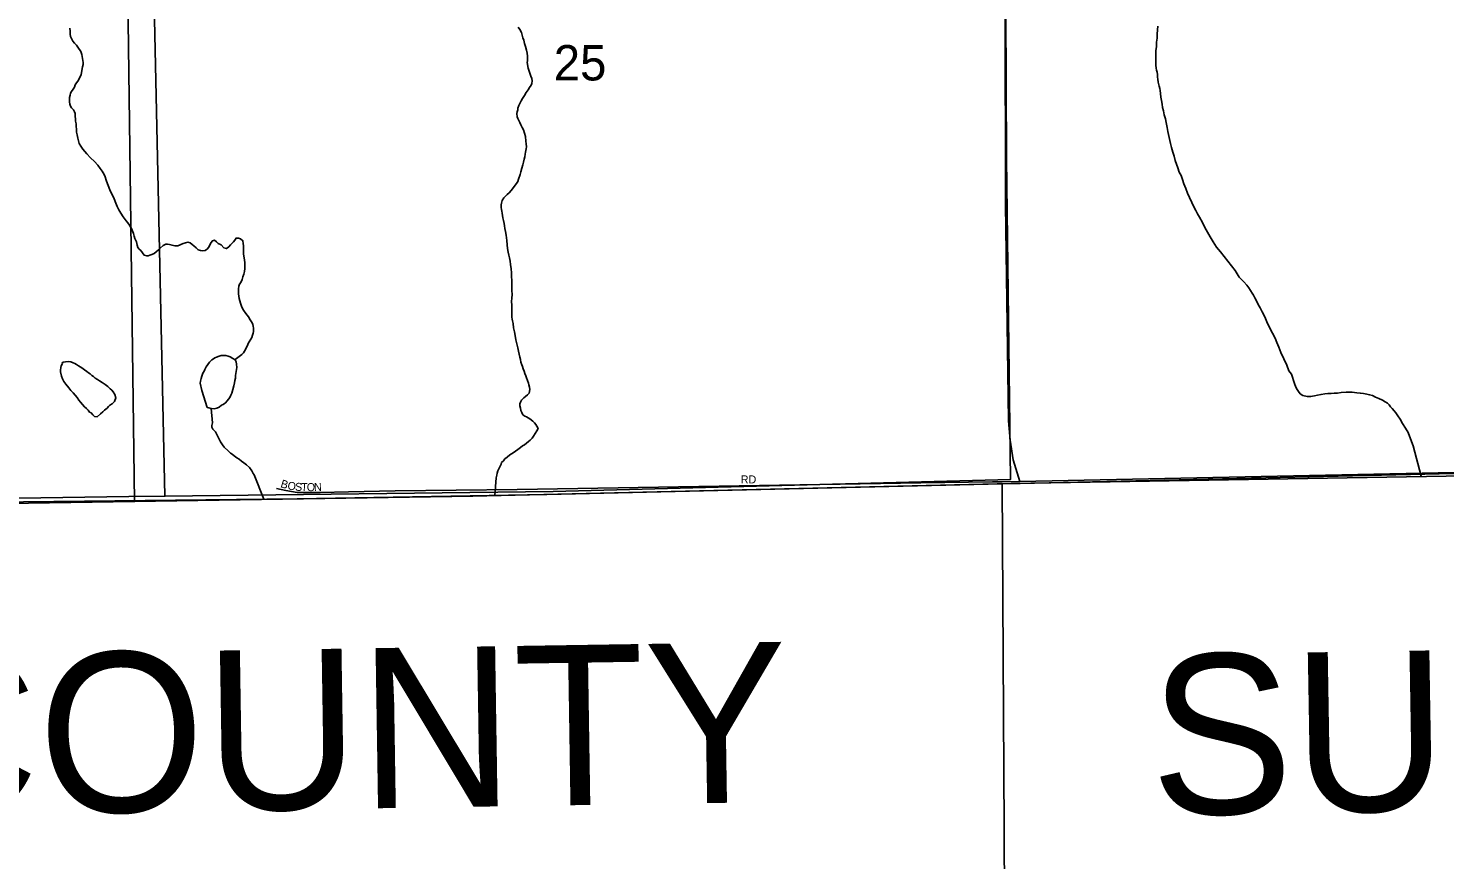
# Model space of a CAD drawing. Extents: x 2010165 to 2382125, y 1060529 to 1407316.
# Drawn here: x 2186541 to 2195389, y 1192490 to 1197681 of the extents above; entities that cross this region are included whole.
import ezdxf

# ---------------------------------------------------------------- set-up
doc = ezdxf.new("R2010")
doc.units = 0
for name, color, linetype in [('GM_X_Adjacent_County', 7, 'Continuous'), ('GM_X_Adjacent_County_Text', 7, 'Continuous'), ('GM_X_City_Street', 7, 'Continuous'), ('GM_X_City_Street_Text', 7, 'Continuous'), ('GM_X_Corporation', 7, 'Continuous'), ('GM_X_County', 7, 'Continuous'), ('GM_X_Major_River', 7, 'Continuous'), ('GM_X_Minor_Lake', 7, 'Continuous'), ('GM_X_Minor_River', 7, 'Continuous'), ('GM_X_Section', 7, 'Continuous'), ('GM_X_Section_Text', 7, 'Continuous'), ('GM_X_State_Route', 7, 'Continuous')]:
    doc.layers.add(name, color=color, linetype=linetype)

msp = doc.modelspace()

# ---------------------------------------------------------------- linework, layer by layer
at = {"layer": 'GM_X_Adjacent_County'}
for points in [[(2192594.1, 1158494.9), (2192604.3, 1162456.4), (2192620.3, 1166969.1), (2192629.9, 1167519.5), (2192631.2, 1170403.5), (2192632.8, 1173672.8), (2192633.8, 1175629.5), (2192671.1, 1181169.3), (2192669.3, 1184775.1), (2192667.8, 1187766.9), (2192660.9, 1188884.7), (2192638, 1192623.1), (2192637, 1192687), (2192624.5, 1194837.8), (2192737.6, 1194839.7), (2198605.6, 1194974.2)], [(2192671.1, 1181169.3), (2192669.3, 1184775.1), (2192667.8, 1187766.9), (2192660.9, 1188884.7), (2192638, 1192623.1), (2192637, 1192687), (2192624.5, 1194837.8), (2192096.3, 1194825.3), (2189780.1, 1194770.1), (2188219.8, 1194742.8), (2183281.7, 1194689.2), (2183037.7, 1194685.2), (2182925.1, 1194679.5), (2182885.3, 1194673), (2182859.5, 1194657.8), (2180868.9, 1194626.6), (2178432, 1194588.4)]]:
    msp.add_lwpolyline(points, dxfattribs=at)
at = {"layer": 'GM_X_City_Street'}
for points in [[(2192734.1, 1194851.8), (2196656.4, 1194933.6)], [(2188364.8, 1194783.1), (2188542, 1194786.7), (2188832, 1194792.7), (2189593.9, 1194801.8), (2192115.6, 1194843.8), (2192565.3, 1194850), (2192624.1, 1194850.3), (2192734.1, 1194851.8)], [(2188091.4, 1194807.8), (2188150.3, 1194794.2), (2188221.4, 1194782.2), (2188223.3, 1194782.1), (2188303, 1194781.8), (2188364.8, 1194783.1)]]:
    msp.add_lwpolyline(points, dxfattribs=at)
at = {"layer": 'GM_X_Corporation'}
for points in [[(2204447.2, 1221938.7), (2204662.3, 1210529.8), (2204445.3, 1208317.3), (2199872.3, 1208332.6), (2199834.9, 1208326), (2199654.4, 1208314.4), (2199497, 1208304.3), (2197215.9, 1208288.2), (2196205.1, 1208275.6), (2196632.3, 1194905.5), (2192680.8, 1194838.8), (2189318.2, 1194759.1), (2187205, 1194725.9), (2187027.1, 1208132.6), (2187013.9, 1213879), (2186978.3, 1216841.2), (2186941.3, 1219753.4), (2186933.5, 1220238.7), (2186923.4, 1220744.1), (2186878.7, 1221701)], [(2186878.7, 1221701), (2186923.4, 1220744.1), (2186933.5, 1220238.7), (2186941.3, 1219753.4), (2186978.3, 1216841.2), (2187013.9, 1213879), (2187027.1, 1208132.6), (2187205, 1194725.9), (2177123.5, 1194567.9), (2176176.5, 1194580.3), (2174206.9, 1194531), (2167776.4, 1194381.4), (2165054.7, 1194304.8), (2164968.9, 1199659.4), (2164935.2, 1207756.2), (2164931.8, 1207897.8), (2164930.1, 1208081.5), (2164898.5, 1211429), (2164844.7, 1216037.6), (2164832.8, 1218637), (2164895.8, 1221436.7)]]:
    msp.add_lwpolyline(points, dxfattribs=at)
at = {"layer": 'GM_X_County'}
msp.add_lwpolyline([(2198605.6, 1194974.2), (2192737.6, 1194839.7), (2192624.5, 1194837.8), (2192096.3, 1194825.3), (2189780.1, 1194770.1), (2188219.8, 1194742.8), (2183281.7, 1194689.2), (2183037.7, 1194685.2), (2182925.1, 1194679.5), (2182885.3, 1194673), (2182859.5, 1194657.8), (2180868.9, 1194626.6), (2178432, 1194588.4)], dxfattribs=at)
at = {"layer": 'GM_X_Major_River'}
for points in [[(2186821.4, 1197302.3), (2186829.1, 1197314.6), (2186834.7, 1197328.8), (2186842.4, 1197341), (2186850.1, 1197351.3), (2186855.9, 1197361.5), (2186861.6, 1197371.7), (2186867.4, 1197381.8), (2186871, 1197394), (2186879.8, 1197440.4), (2186883.4, 1197456.6), (2186883.1, 1197468.6), (2186882.7, 1197480.6), (2186880.4, 1197492.6), (2186878, 1197506.6), (2186875.7, 1197518.6), (2186871.4, 1197530.5), (2186867.1, 1197540.5), (2186858.8, 1197552.3), (2186850.4, 1197564.1), (2186842.1, 1197575.9), (2186829.7, 1197589.7), (2186819.3, 1197601.4), (2186810.9, 1197617.3), (2186804.5, 1197631.2), (2186802.1, 1197645.2), (2186801.6, 1197663.2), (2186801.1, 1197683.3)], [(2187823.6, 1196348.8), (2187813.8, 1196340.5), (2187804.1, 1196330.2), (2187794.4, 1196317.9), (2187778.7, 1196305.5), (2187762.5, 1196311.1), (2187746, 1196328.7), (2187727.7, 1196338.3), (2187717.4, 1196348), (2187705.1, 1196357.8), (2187691.1, 1196355.4), (2187683.4, 1196343.1), (2187677.7, 1196332.9), (2187670.1, 1196318.7), (2187660.4, 1196304.4), (2187646.7, 1196294), (2187630.7, 1196291.5), (2187616.6, 1196293.2), (2187602.4, 1196298.8), (2187590.1, 1196310.6), (2187575.7, 1196322.2), (2187565.4, 1196332), (2187553.1, 1196341.7), (2187537, 1196345.3), (2187523, 1196342.9), (2187509.1, 1196338.5), (2187475.4, 1196323.6), (2187457.4, 1196323.1), (2187439.2, 1196326.7), (2187423, 1196332.3), (2187411, 1196333.9), (2187400.9, 1196333.7), (2187383.1, 1196325.2), (2187365.5, 1196308.7), (2187353.8, 1196298.3), (2187340.1, 1196285.9), (2187326.3, 1196275.5), (2187312.5, 1196269.1), (2187300.5, 1196264.8), (2187290.6, 1196260.5), (2187280.6, 1196260.2), (2187264.4, 1196265.8), (2187254, 1196279.6), (2187243.6, 1196293.4), (2187233.3, 1196303.2), (2187225, 1196313), (2187220.7, 1196326.9), (2187216.1, 1196348.9), (2187207.5, 1196368.8), (2187203.1, 1196382.7), (2187198.6, 1196400.6), (2187194.3, 1196410.6), (2187187.9, 1196426.5), (2187181.6, 1196438.4), (2187173.2, 1196452.2), (2187162.8, 1196466), (2187152.4, 1196479.8), (2187133.7, 1196503.3), (2187119, 1196527.1), (2187106.4, 1196548.8), (2187095.8, 1196568.6), (2187087.2, 1196590.5), (2187076.5, 1196616.3), (2187050.9, 1196673.9), (2187040.2, 1196699.7), (2187029.4, 1196727.5), (2187018.4, 1196761.3), (2187007.9, 1196779.1), (2187001.7, 1196789), (2186989.2, 1196806.8), (2186974.6, 1196826.5), (2186953.9, 1196850), (2186929.2, 1196873.5), (2186906.5, 1196897), (2186881.6, 1196926.4), (2186869.1, 1196946.2), (2186858.6, 1196962), (2186854.2, 1196977.9), (2186849.7, 1196995.8), (2186847.2, 1197015.9), (2186842.7, 1197033.8), (2186842.2, 1197051.9), (2186839.7, 1197067.9), (2186839.2, 1197085.9), (2186836.8, 1197101.9), (2186836.4, 1197118), (2186834.1, 1197128), (2186833.8, 1197140), (2186833.5, 1197150), (2186829.2, 1197160), (2186822.9, 1197171.8), (2186810.5, 1197185.6), (2186804.2, 1197195.5), (2186799.9, 1197207.4), (2186799.4, 1197223.4), (2186799.1, 1197237.5), (2186798.7, 1197249.5), (2186802.4, 1197263.7), (2186804, 1197275.8), (2186811.7, 1197288), (2186821.4, 1197302.3)], [(2187832.4, 1195612.8), (2187874.7, 1195645.4), (2187884.4, 1195655.7), (2187892.2, 1195665.9), (2187897.9, 1195676.1), (2187903.6, 1195690.3), (2187909.3, 1195700.5), (2187915, 1195712.7), (2187938, 1195751.4), (2187941.6, 1195765.6), (2187945.3, 1195777.8), (2187947, 1195787.8), (2187946.8, 1195797.9), (2187948.5, 1195810), (2187946.1, 1195821.9), (2187943.9, 1195831.9), (2187939.6, 1195841.9), (2187927, 1195861.6), (2187916.5, 1195879.4), (2187908.2, 1195891.2), (2187899.9, 1195901.1), (2187885.3, 1195920.7), (2187874.8, 1195940.6), (2187866.1, 1195964.4), (2187859.3, 1195994.3), (2187854.4, 1196024.3), (2187853.6, 1196054.4), (2187857.2, 1196070.6), (2187860.9, 1196082.8), (2187868.6, 1196095), (2187876.1, 1196113.3), (2187881.7, 1196129.5), (2187887.3, 1196145.7), (2187890.8, 1196163.8), (2187894.3, 1196182), (2187893.8, 1196200.1), (2187893.3, 1196218.1), (2187888.5, 1196248.1), (2187885.9, 1196272.1), (2187885.3, 1196292.2), (2187884.8, 1196310.3), (2187884.5, 1196322.3), (2187884.1, 1196338.4), (2187881.6, 1196354.4), (2187867.3, 1196366), (2187853.1, 1196371.7), (2187839.1, 1196371.3), (2187831.4, 1196359.1), (2187823.6, 1196348.8)]]:
    msp.add_lwpolyline(points, dxfattribs=at)
at = {"layer": 'GM_X_Minor_Lake'}
for points in [[(2187615.1, 1195465.9), (2187616.5, 1195477.9), (2187620.1, 1195494.1), (2187625.7, 1195508.3), (2187631.2, 1195528.5), (2187638.9, 1195540.8), (2187644.6, 1195551), (2187652.2, 1195567.2), (2187661.9, 1195581.6), (2187673.5, 1195595.9), (2187687.1, 1195610.3), (2187697, 1195616.6), (2187706.9, 1195622.9), (2187716.8, 1195627.2), (2187732.6, 1195633.6), (2187746.6, 1195638), (2187756.6, 1195638.3), (2187774.6, 1195638.7), (2187788.7, 1195635.1), (2187802.9, 1195629.4), (2187819.2, 1195619.8), (2187833.5, 1195612.2), (2187839.9, 1195598.3), (2187842.2, 1195584.3), (2187842.8, 1195564.2), (2187836.1, 1195513.8), (2187834.6, 1195495.7), (2187831, 1195481.6), (2187829.4, 1195467.5), (2187825.8, 1195449.3), (2187818.5, 1195425), (2187813.1, 1195402.8), (2187805.4, 1195390.6), (2187799.7, 1195376.3), (2187784.2, 1195355.9), (2187772.5, 1195343.5), (2187758.8, 1195333.1), (2187748.9, 1195328.8), (2187733.2, 1195316.4), (2187719.3, 1195310), (2187701.4, 1195305.5), (2187683.3, 1195307), (2187669.2, 1195310.7), (2187659, 1195314.4), (2187624.1, 1195419.9)], [(2186755.3, 1195587.8), (2186745.7, 1195573.5), (2186744, 1195563.4), (2186742.4, 1195547.3), (2186742.7, 1195537.3), (2186747.4, 1195509.3), (2186753.9, 1195493.4), (2186762.4, 1195475.6), (2186774.8, 1195459.8), (2186793.5, 1195436.2), (2186806, 1195420.5), (2186820.4, 1195404.8), (2186832.8, 1195391.1), (2186845.3, 1195375.3), (2186855.7, 1195359.5), (2186868.1, 1195345.8), (2186880.5, 1195332.1), (2186892.9, 1195318.3), (2186905.3, 1195306.6), (2186915.6, 1195296.9), (2186923.9, 1195285), (2186934.1, 1195279.3), (2186944.4, 1195267.5), (2186954.7, 1195257.7), (2186970.8, 1195256.1), (2186992.4, 1195274.8), (2187006.1, 1195287.2), (2187017.8, 1195297.5), (2187033.5, 1195310), (2187041.3, 1195320.2), (2187051.1, 1195328.5), (2187064.9, 1195336.9), (2187078.5, 1195351.3), (2187088, 1195373.7), (2187081.3, 1195395.6), (2187070.9, 1195411.4), (2187062.6, 1195421.2), (2187052.3, 1195431), (2187037.9, 1195444.7), (2187021.6, 1195456.3), (2187003.1, 1195469.8), (2186984.8, 1195479.4), (2186972.5, 1195489.1), (2186958.3, 1195496.8), (2186948, 1195506.5), (2186937.8, 1195514.3), (2186927.5, 1195524.1), (2186917.3, 1195529.8), (2186907.1, 1195537.6), (2186892.7, 1195549.3), (2186876.4, 1195560.9), (2186854, 1195574.3), (2186841.7, 1195582.1), (2186831.5, 1195587.8), (2186821.4, 1195591.6), (2186807.2, 1195599.2), (2186791.1, 1195600.8), (2186773.1, 1195598.3), (2186759.1, 1195595.9), (2186751.3, 1195589.7)], [(2187624.1, 1195419.9), (2187615.1, 1195465.9)]]:
    msp.add_lwpolyline(points, dxfattribs=at)
at = {"layer": 'GM_X_Minor_River'}
for points in [[(2189527, 1196389.6), (2189522.3, 1196413.6), (2189517.8, 1196431.6), (2189515.4, 1196447.6), (2189512.9, 1196463.6), (2189508.5, 1196481.5), (2189506, 1196497.5), (2189503.6, 1196513.5), (2189501.2, 1196527.5), (2189498.9, 1196539.5), (2189496.6, 1196549.5), (2189494.2, 1196563.5), (2189495.8, 1196579.6), (2189497.5, 1196589.7), (2189501.1, 1196605.8), (2189510.7, 1196622.1), (2189532.2, 1196642.8), (2189543.9, 1196655.1), (2189557.5, 1196669.6), (2189590.5, 1196712.6), (2189598.1, 1196724.8), (2189603.8, 1196739), (2189613, 1196769.4), (2189618.6, 1196785.6), (2189624, 1196807.8), (2189629.4, 1196828.1), (2189635, 1196846.3), (2189638.5, 1196864.4), (2189642.1, 1196878.6), (2189645.7, 1196894.8), (2189647.3, 1196908.8), (2189649, 1196918.9), (2189650.8, 1196929), (2189652.5, 1196941.1), (2189652, 1196959.2), (2189649.5, 1196977.2), (2189646.7, 1197005.2), (2189640.1, 1197027.1), (2189633.6, 1197047), (2189627.1, 1197062.9), (2189618.7, 1197078.8), (2189612.3, 1197092.7), (2189605.9, 1197106.6), (2189599.6, 1197118.4), (2189595.3, 1197128.4), (2189592.7, 1197150.4), (2189594.4, 1197160.4), (2189598.1, 1197172.6), (2189599.8, 1197182.7), (2189605.4, 1197198.9), (2189613, 1197215.2), (2189620.6, 1197229.4), (2189628.3, 1197243.7), (2189639.8, 1197262), (2189651.3, 1197280.4), (2189662.9, 1197296.8), (2189672.6, 1197311.1), (2189682.1, 1197327.4), (2189685.9, 1197337.6), (2189689.5, 1197353.7), (2189687.1, 1197367.7), (2189680.6, 1197383.6), (2189674.1, 1197401.5), (2189667.6, 1197419.4), (2189663.3, 1197433.3), (2189658.3, 1197467.3), (2189660, 1197479.4), (2189659.6, 1197493.5), (2189659.2, 1197507.5), (2189656.8, 1197525.5), (2189652.2, 1197545.5), (2189647.6, 1197567.4), (2189641.1, 1197587.4), (2189636.5, 1197607.3), (2189630.1, 1197623.2), (2189625.6, 1197639.2), (2189621.2, 1197655.1), (2189612.6, 1197675), (2189602.2, 1197688.7)], [(2193596.4, 1197695.6), (2193595.1, 1197671.4), (2193593.8, 1197645.3), (2193592.5, 1197619.2), (2193589.1, 1197595), (2193587.8, 1197568.8), (2193584.6, 1197540.6), (2193585.2, 1197516.6), (2193583.9, 1197492.4), (2193584.4, 1197472.4), (2193584.9, 1197452.3), (2193587.5, 1197432.3), (2193589.8, 1197420.3), (2193592.2, 1197408.3), (2193594.6, 1197392.3), (2193595, 1197376.3), (2193597.4, 1197364.3), (2193599.8, 1197346.3), (2193602.1, 1197336.3), (2193604.6, 1197320.3), (2193608.9, 1197306.4), (2193611.3, 1197292.4), (2193613.8, 1197274.4), (2193616.4, 1197252.3), (2193619, 1197230.3), (2193623.6, 1197208.4), (2193626.2, 1197186.3), (2193632.8, 1197166.4), (2193637.5, 1197140.5), (2193644.1, 1197116.5), (2193648.8, 1197092.6), (2193655.6, 1197062.6), (2193660.3, 1197036.7), (2193676.3, 1196962.8), (2193683.1, 1196936.8), (2193691.8, 1196909), (2193698.6, 1196883.1), (2193705.3, 1196857.1), (2193713.9, 1196833.3), (2193722.6, 1196809.4), (2193731.3, 1196783.5), (2193741.9, 1196761.7), (2193750.6, 1196737.8), (2193759.4, 1196710), (2193772.1, 1196682.2), (2193783, 1196652.4), (2193795.8, 1196624.6), (2193808.6, 1196594.8), (2193821.4, 1196567), (2193834, 1196543.3), (2193844.6, 1196523.5), (2193857.2, 1196501.7), (2193876.2, 1196468.1), (2193891, 1196438.4), (2193907.9, 1196408.7), (2193924.7, 1196379), (2193943.6, 1196347.4), (2193964.5, 1196315.8), (2193989.4, 1196286.3), (2194012.2, 1196256.8), (2194035.1, 1196227.3), (2194057.9, 1196197.8), (2194080.8, 1196168.3), (2194106, 1196126.8), (2194134.8, 1196097.4), (2194153.4, 1196077.8), (2194165.9, 1196060.1), (2194176.4, 1196044.3)], [(2189454.7, 1194764.6), (2189463.6, 1194874), (2189467.1, 1194890.1), (2189470.8, 1194904.3), (2189474.4, 1194918.5), (2189482, 1194934.7), (2189495.4, 1194959.2), (2189497.1, 1194969.2), (2189508.9, 1194979.6), (2189518.5, 1194991.9), (2189532.2, 1195004.3), (2189549.9, 1195018.8), (2189569.6, 1195031.4), (2189585.4, 1195041.8), (2189599.1, 1195052.2), (2189614.9, 1195062.7), (2189628.6, 1195073.1), (2189640.5, 1195081.4), (2189652.3, 1195089.8), (2189666, 1195100.2), (2189675.8, 1195108.5), (2189689.5, 1195122.9), (2189697.2, 1195135.1), (2189706.7, 1195151.5), (2189718.3, 1195167.8), (2189726, 1195182.1), (2189717.5, 1195197.9), (2189711.2, 1195207.8), (2189702.9, 1195217.6), (2189692.7, 1195227.4), (2189674.2, 1195243), (2189664, 1195248.7), (2189653.8, 1195254.5), (2189643.7, 1195260.2), (2189629.4, 1195267.9), (2189625, 1195281.8), (2189618.6, 1195295.7), (2189616.2, 1195309.7), (2189611.9, 1195323.7), (2189611.5, 1195335.7), (2189615.2, 1195347.8), (2189622.9, 1195360.1), (2189636.6, 1195374.5), (2189646.4, 1195382.8), (2189660.1, 1195393.2), (2189669.9, 1195403.5), (2189673.3, 1195425.7), (2189672.9, 1195439.7), (2189668.5, 1195455.7), (2189666.2, 1195465.6), (2189659.7, 1195481.5), (2189653.2, 1195499.4), (2189648.9, 1195511.4), (2189642.5, 1195525.3), (2189638.1, 1195541.2), (2189631.7, 1195555.1), (2189627.3, 1195569), (2189625, 1195581), (2189618.5, 1195596.9), (2189616.1, 1195612.9), (2189611.7, 1195628.9), (2189607.2, 1195646.8), (2189602.7, 1195664.8), (2189598.1, 1195686.7), (2189593.4, 1195710.7), (2189586.7, 1195736.6), (2189582, 1195762.6), (2189577.3, 1195786.6), (2189572.7, 1195810.6), (2189569.9, 1195838.6), (2189565.5, 1195854.5), (2189563.2, 1195864.5), (2189560.8, 1195878.5), (2189562.4, 1195892.6), (2189562.1, 1195904.6), (2189561.8, 1195916.7), (2189560.7, 1195956.8), (2189560.3, 1195970.9), (2189560, 1195980.9), (2189561.8, 1195991), (2189561.5, 1196001), (2189563.1, 1196015.1), (2189562.9, 1196025.1), (2189562.5, 1196037.2), (2189562.2, 1196049.2), (2189561.8, 1196063.3), (2189561.6, 1196073.3), (2189561.2, 1196087.3), (2189560.6, 1196109.4), (2189560.1, 1196129.5), (2189559.4, 1196153.6), (2189556.7, 1196179.6), (2189554, 1196205.6), (2189551.4, 1196227.6), (2189546.8, 1196247.6), (2189542.4, 1196265.6), (2189537.9, 1196283.5), (2189535.3, 1196305.5), (2189532.6, 1196329.6), (2189529.9, 1196355.6), (2189527, 1196389.6)], [(2194176.4, 1196044.3), (2194186.8, 1196028.5), (2194195.2, 1196014.7), (2194203.6, 1195998.8), (2194214.2, 1195979), (2194224.8, 1195957.2), (2194235.4, 1195935.4), (2194248.1, 1195911.6), (2194265, 1195880), (2194277.9, 1195848.2), (2194294.9, 1195812.5), (2194313.9, 1195776.8), (2194330.7, 1195747.2), (2194341.5, 1195719.3), (2194352.4, 1195689.5), (2194365.2, 1195657.7), (2194403.5, 1195578.4), (2194416.5, 1195542.6), (2194431.1, 1195520.9), (2194437.6, 1195503), (2194444.1, 1195483.1), (2194450.7, 1195463.2), (2194459.3, 1195441.3), (2194467.8, 1195425.5), (2194476.1, 1195413.7), (2194486.5, 1195399.9), (2194502.8, 1195388.3), (2194529, 1195382.9), (2194551.2, 1195381.5), (2194575.1, 1195386.2), (2194595, 1195390.7), (2194616.9, 1195395.3), (2194640.9, 1195397.9), (2194658.9, 1195400.4), (2194679, 1195400.9), (2194698.9, 1195403.5), (2194719, 1195404), (2194743, 1195406.6), (2194773, 1195409.4), (2194811.1, 1195408.4), (2194839.3, 1195405.2), (2194861.4, 1195403.7), (2194881.5, 1195400.3), (2194901.7, 1195396.8), (2194919.8, 1195393.2), (2194938, 1195387.7), (2194956.3, 1195378.1), (2194978.6, 1195368.7), (2195000.9, 1195359.2), (2195017.2, 1195349.6), (2195031.5, 1195339.9), (2195041.8, 1195330.2), (2195050.1, 1195318.3), (2195060.5, 1195306.6), (2195072.9, 1195292.8), (2195083.2, 1195281.1), (2195095.8, 1195261.3), (2195110.4, 1195241.6), (2195125.1, 1195213.9), (2195144, 1195184.3), (2195160.8, 1195156.6), (2195175.9, 1195116.9), (2195193.1, 1195075.1), (2195242.5, 1194884.4)], [(2188012.1, 1194740.9), (2187951.1, 1194892.4), (2187944.9, 1194902.3), (2187936.4, 1194918.1), (2187921.8, 1194937.8), (2187903.3, 1194955.4), (2187887, 1194967), (2187872.6, 1194978.7), (2187858.3, 1194990.4), (2187844, 1195000), (2187827.6, 1195011.6), (2187815.3, 1195021.3), (2187805.1, 1195029.1), (2187788.7, 1195042.7), (2187764, 1195066.2), (2187753.6, 1195080), (2187741, 1195099.7), (2187726.2, 1195127.4), (2187711.3, 1195161.2), (2187692.8, 1195178.8), (2187688.4, 1195190.7), (2187688.2, 1195200.7), (2187691.7, 1195216.9), (2187682.9, 1195307.1)]]:
    msp.add_lwpolyline(points, dxfattribs=at)
at = {"layer": 'GM_X_Section'}
for points in [[(2187275.3, 1200238.2), (2187394.1, 1194759.7), (2187168.3, 1194757.7), (2184550.9, 1194718.9), (2182414, 1194680.4), (2182206.7, 1200204.6)], [(2192632.1, 1200277.7), (2192640.4, 1199176.3), (2192652.6, 1196868), (2192676.2, 1194863.4), (2189820, 1194788.8), (2187394.1, 1194759.7), (2187275.3, 1200238.2)]]:
    msp.add_lwpolyline(points, close=True, dxfattribs=at)
at = {"layer": 'GM_X_State_Route'}
msp.add_lwpolyline([(2192734.1, 1194851.8), (2192694.1, 1194985.9), (2192674.1, 1195109.4), (2192664.1, 1195230.7), (2192646, 1196579.6), (2192639.3, 1200294.1)], dxfattribs=at)

# ---------------------------------------------------------------- texts
at = {"layer": 'GM_X_Adjacent_County_Text'}
for s, rotation, p in [('SUMMIT COUNTY', 0.95319, (2193555.6, 1192767.3)), ('MEDINA COUNTY', 0.89203, (2180073.4, 1192676.1))]:
    msp.add_text(s, height=1000, rotation=rotation, dxfattribs=at).set_placement(p)
at = {"layer": 'GM_X_City_Street_Text'}
for s, rotation, p in [('B', 342.75174, (2188113, 1194816.9)), ('O', 349.29604, (2188156.9, 1194803.6)), ('S', 355.10108, (2188205.6, 1194794.7)), ('T', 359.3928, (2188244.8, 1194791.5)), ('O', 0.43787, (2188281, 1194791.1)), ('N', 1.93137, (2188326.4, 1194791.5)), ('RD', 0.00001, (2190991.8, 1194839.4))]:
    msp.add_text(s, height=50, rotation=rotation, dxfattribs=at).set_placement(p)
at = {"layer": 'GM_X_Section_Text'}
msp.add_text('25', height=221, rotation=0.00001, dxfattribs=at).set_placement((2189823.6, 1197356))

doc.saveas('drawing.dxf')
